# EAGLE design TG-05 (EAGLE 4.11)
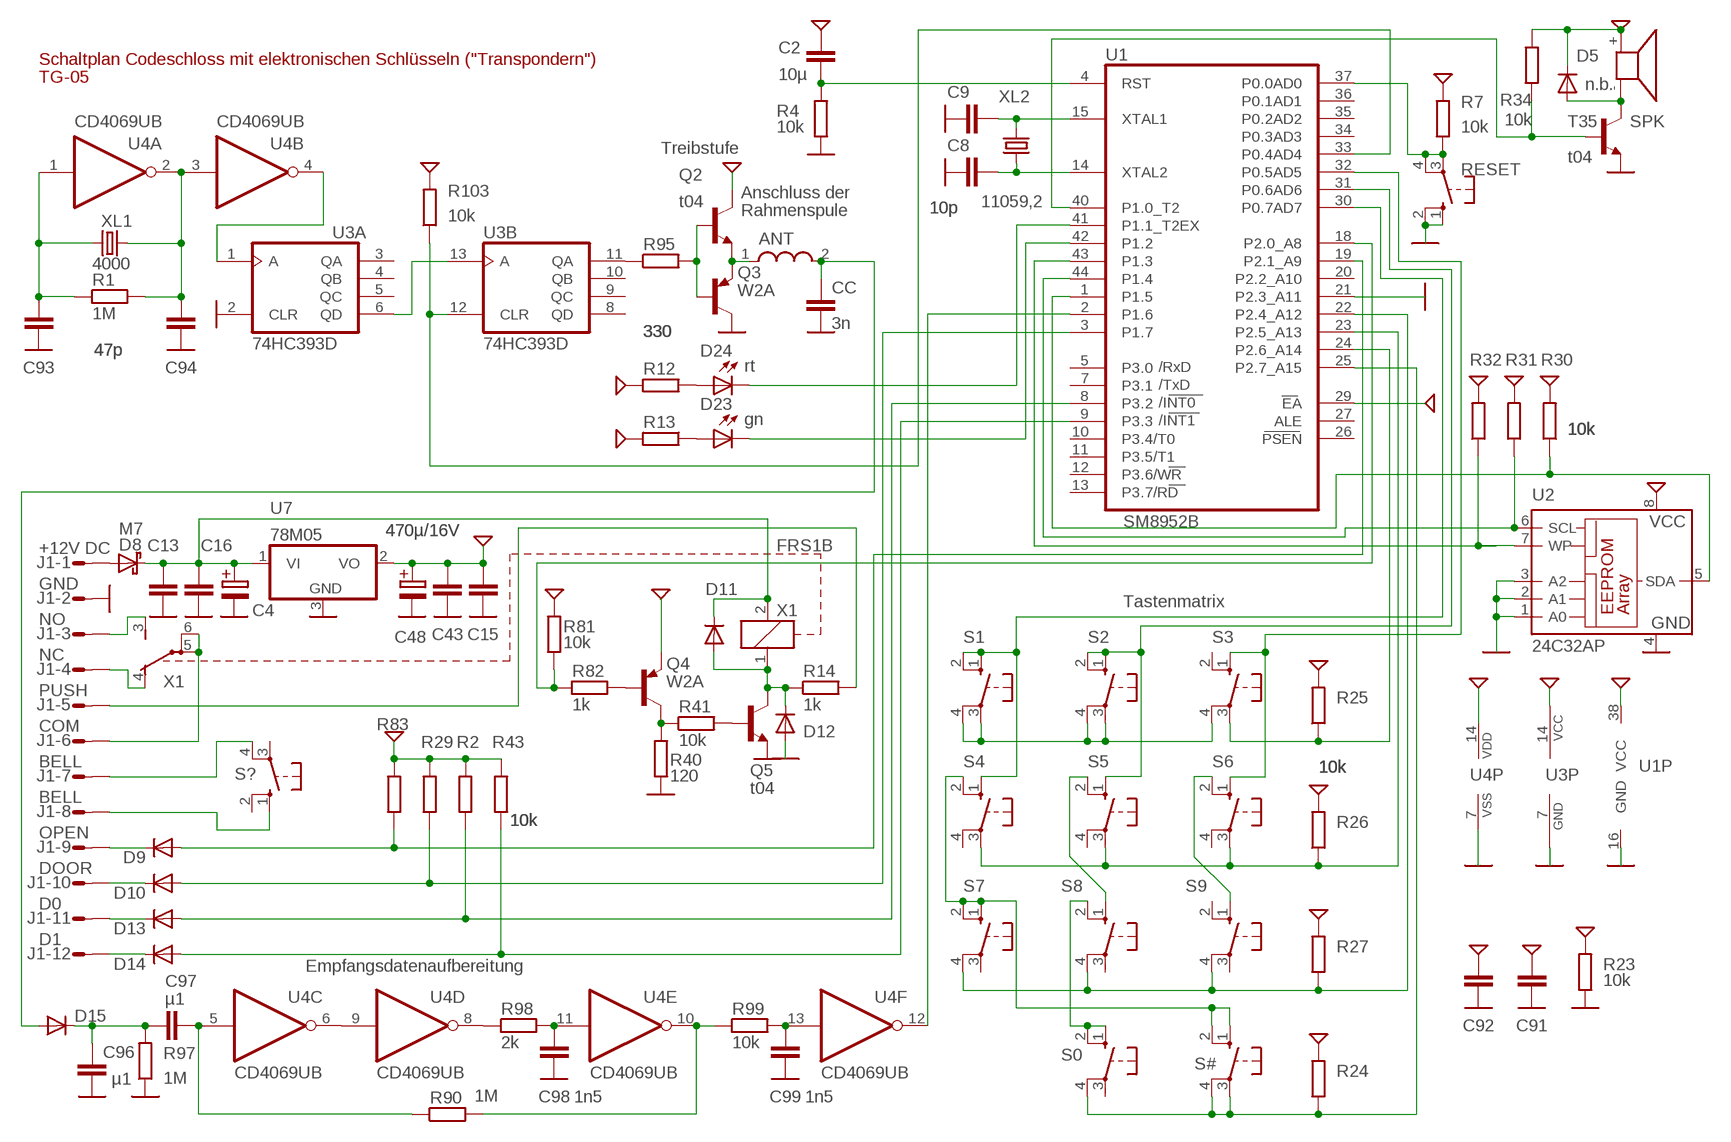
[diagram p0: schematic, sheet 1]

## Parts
ANT  L1206  [1206]
C2  10µ  C0805  [0805]
C4  470µ/16V  E01-5  [E01-5]
C8  10p  C0603  [0603]
C9  10p  C0603  [0603]
C13  C0603  [0603]
C15  C0603  [0603]
C16  C0603  [0603]
C43  C0603  [0603]
C48  470µ/16V  E01-5  [E01-5]
C91  C0603  [0603]
C92  C0603  [0603]
C93  47p  C0603  [0603]
C94  47p  C0603  [0603]
C96  µ1  C0603  [0603]
C97  µ1  C0603  [0603]
C98  1n5  C0603  [0603]
C99  1n5  C0603  [0603]
CC  3n  C1206  [1206]
D5  n.b.  D  [MINIMELF]
D8  M7  DSB  [SMB]
D9  D  [MINIMELF]
D10  D  [MINIMELF]
D11  D  [MINIMELF]
D12  D  [MINIMELF]
D13  D  [MINIMELF]
D14  D  [MINIMELF]
D15  D  [MINIMELF]
D23  gn  LEDCHIP-LED0805  [CHIP-LED0805]
D24  rt  LEDCHIP-LED0805  [CHIP-LED0805]
J1  S12P  [S12P]
Q2  t04  NPN23BEC  [SOT23]
Q3  W2A  PNP23BEC  [SOT23]
Q4  W2A  PNP23BEC  [SOT23]
Q5  t04  NPN23BEC  [SOT23]
R1  1M  R0603  [0603]
R2  10k  R0603  [0603]
R4  10k  R0603  [0603]
R7  10k  R0603  [0603]
R12  330  R0603  [0603]
R13  330  R0603  [0603]
R14  1k  R0603  [0603]
R23  10k  R0603  [0603]
R24  10k  R0603  [0603]
R25  10k  R0603  [0603]
R26  10k  R0603  [0603]
R27  10k  R0603  [0603]
R29  10k  R0603  [0603]
R30  10k  R0603  [0603]
R31  10k  R0603  [0603]
R32  10k  R0603  [0603]
R34  10k  R0603  [0603]
R40  120  R0603  [0603]
R41  10k  R0603  [0603]
R43  10k  R0603  [0603]
R81  10k  R0603  [0603]
R82  1k  R0603  [0603]
R83  10k  R0603  [0603]
R90  1M  R0603  [0603]
R95  330  R0603  [0603]
R97  1M  R0603  [0603]
R98  2k  R0603  [0603]
R99  10k  R0603  [0603]
R103  10k  R0603  [0603]
RESET  10-XX  [B3F-10XX]
S0  10-XXSMD  [B3F-10SMD]
S1  10-XXSMD  [B3F-10SMD]
S2  10-XXSMD  [B3F-10SMD]
S3  10-XXSMD  [B3F-10SMD]
S4  10-XXSMD  [B3F-10SMD]
S5  10-XXSMD  [B3F-10SMD]
S6  10-XXSMD  [B3F-10SMD]
S7  10-XXSMD  [B3F-10SMD]
S8  10-XXSMD  [B3F-10SMD]
S9  10-XXSMD  [B3F-10SMD]
S#  10-XXSMD  [B3F-10SMD]
S?  10-XXSMD  [B3F-10SMD]
SPK  KSS1201  [KSS1201]
T35  t04  NPN23BEC  [SOT23]
U1  SM8952B  AT89C8252Q  [PQFP44]
U2  24C32AP  [DIL8]
U3  74HC393D  74LS393D  [SO14]
U4  CD4069UB  4069D  [SO14]
U7  78M05  7805DT  [TO252]
X1  FRS1B  [FRS1B]
XL1  4000  CRYSTALS  [HC49/S]
XL2  11059,2  CRYSTALS  [HC49/S]

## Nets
5P: C2.1 C15.1 C43.1 C48.+ C91.1 C92.1 D5.K Q2.3(C) Q4.2(E) R2.2 R7.2 R12.2 R13.2 R23.2 R24.2 R25.2 R26.2 R27.2 R29.2 R30.2 R31.2 R32.2 R34.2 R43.2 R81.2 R83.2 R103.2 SPK.+ U1.29(EA) U1.38(VCC) U2.8(VCC) U3.14(P:VCC) U4.14(P:VDD) U7.2(VO)
12P: C4.+ C13.1 C16.1 D8.1(K) D11.K U7.1(VI) X1.2
GND: C4.- C8.2 C9.2 C13.2 C15.2 C16.2 C43.2 C48.- C91.2 C92.2 C93.2 C94.2 C96.2 C98.2 C99.2 CC.2 D12.A J1.2 Q3.3(C) Q5.2(E) R4.1 R23.1 R40.1 R97.1 RESET.1(S) RESET.2(S) T35.2(E) U1.16(GND) U1.21(P2.3_A11) U2.1(A0) U2.2(A1) U2.3(A2) U2.4(GND) U3.2(A:CLR) U3.7(P:GND) U4.7(P:VSS) U7.3(GND)
N$1: ANT.2 CC.1 D15.A
N$2: ANT.1 Q2.2(E) Q3.2(E)
N$3: D8.2(A) J1.1
N$4: D11.A D12.K Q5.3(C) R14.1 X1.1
N$5: C8.1 U1.14(XTAL2) XL2.1
N$6: C9.1 U1.15(XTAL1) XL2.2
N$7: R32.1 U1.43(P1.3) U2.7(WP)
N$8: R34.1 T35.1(B) U1.40(P1.0_T2)
N$9: D24.A R12.1
N$10: D23.A R13.1
N$11: Q5.1(B) R41.2
N$12: Q4.3(C) R40.2 R41.1
N$13: R25.1 S3.3(P) U1.24(P2.6_A14)
N$14: S5.2(S) S8.1(S)
N$15: S1.1(S) S1.2(S) S4.1(S) U1.30(P0.7AD7)
N$16: R30.1 U1.1(P1.5) U2.5(SDA)
N$17: R31.1 U1.44(P1.4) U2.6(SCL)
N$18: R26.1 S4.3(P) S5.3(P) S6.3(P) U1.23(P2.5_A13)
N$19: D24.C U1.41(P1.1_T2EX)
N$20: J1.8 S?.1(S)
N$21: D23.C U1.42(P1.2)
N$22: S3.1(S) S6.1(S) U1.32(P0.5AD5)
N$23: R7.1 RESET.3(P) RESET.4(P) U1.37(P0.0AD0)
N$24: D5.A SPK.- T35.3(C)
N$25: R27.1 S7.4(P) S8.4(P) S9.4(P) U1.22(P2.4_A12)
N$26: R24.1 S0.4(P) S#.3(P) S#.4(P) U1.25(P2.7_A15)
N$27: D9.K J1.9
N$28: J1.7 S?.4(P)
N$29: D10.K J1.10
N$30: D9.A R83.1 U1.19(P2.1_A9)
N$31: R95.1 U3.11(B:QA)
N$32: Q2.1(B) Q3.1(B) R95.2
N$33: D13.K J1.11
N$34: C96.1 C97.1 D15.K R97.2
N$35: C97.2 R90.1 U4.5(C:I)
N$36: R90.2 R99.1 U4.10(E:O)
N$37: C93.1 R1.1 U4.1(A:I) XL1.2
N$38: C98.1 R98.2 U4.11(E:I)
N$39: R98.1 U4.8(D:O)
N$40: U3.6(A:QD) U3.13(B:A)
N$41: U4.6(C:O) U4.9(D:I)
N$42: J1.3 X1.3(2:S)
N$43: J1.4 X1.4(2:O)
N$44: J1.6 X1.5(2:P) X1.6(2:P)
N$45: D14.K J1.12
N$46: J1.5 R14.2
N$47: C94.1 R1.2 U4.2(A:O) U4.3(B:I) XL1.1
N$48: D10.A R29.1 U1.3(P1.7)
N$49: U3.1(A:A) U4.4(B:O)
N$50: C99.1 R99.2 U4.13(F:I)
N$51: U1.2(P1.6) U4.12(F:O)
N$52: R103.1 U1.33(P0.4AD4) U3.12(B:CLR)
N$53: D13.A R2.1 U1.8(P3.2)
N$54: D14.A R43.1 U1.9(P3.3)
N$55: Q4.1(B) R82.2
N$56: R81.1 R82.1 U1.18(P2.0_A8)
N$57: S2.1(S) S2.2(S) S5.1(S) U1.31(P0.6AD6)
N$58: S6.2(S) S9.1(S)
N$59: S4.2(S) S7.1(S) S7.2(S) S#.1(S) S#.2(S)
N$60: S0.1(S) S0.2(S) S8.2(S)
N$61: S1.3(P) S1.4(P) S2.3(P) S2.4(P) S3.4(P)
RESET: C2.2 R4.2 U1.4(RST)
Unconnected: S0.3(P) S3.2(S) S4.4(P) S5.4(P) S6.4(P) S7.3(P) S8.3(P) S9.2(S) S9.3(P) S?.2(S) S?.3(P) U1.5(P3.0) U1.7(P3.1) U1.10(P3.4/T0) U1.11(P3.5/T1) U1.12(P3.6/WR) U1.13(P3.7/RD) U1.20(P2.2_A10) U1.26(PSEN) U1.27(ALE) U1.34(P0.3AD3) U1.35(P0.2AD2) U1.36(P0.1AD1) U3.3(A:QA) U3.4(A:QB) U3.5(A:QC) U3.8(B:QD) U3.9(B:QC) U3.10(B:QB)

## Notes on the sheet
- Schaltplan Codeschloss mit elektronischen Schlüsseln ("Transpondern")
- TG-05
- Treibstufe
- Anschluss der
- Rahmenspule
- +12V DC
- GND
- Tastenmatrix
- NO
- NC
- PUSH
- COM
- BELL
- BELL
- OPEN
- DOOR
- D0
- D1
- Empfangsdatenaufbereitung

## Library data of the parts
ANT = Ofen:L: Drossel
C2 C8 C9 C13 C15 C16 C43 C91-C94 C96-C99 CC = Ofen:C: Kondensator
C4 C48 = Ofen:E: Elektrolytkondensator
D5 D9-D15 = Ofen:D: Diode
D8 = Ofen:DS: Schottky-Diode
D23 D24 = led:LED: LED
J1 = con-amp-mt:S12P: AMP MT CONNECTOR
Q2 Q5 T35 = Ofen:NPN: NPN-Transistor Verschiedene Bauformen und Leistungen
Q3 Q4 = Ofen:PNP: PNP-Transistor Verschiedene Bauformen und Leistungen
R1 R2 R4 R7 R12-R14 R23-R27 R29-R32 R34 R40 R41 R43 R81-R83 R90 R95 R97-R99 R103 = Ofen:R: Widerstand
RESET S0 S1-S9 S# S? = Ofen:10-XX: Drucktaster
SPK = buzzer:KSS1201: SPEAKER
U1 = atmel:AT89C*52: MICROCONTROLLER 8 Kbytes FLASH; 2K Bytes EEPROM Compatible with MCS-51 Products at89s8252.pdf
U2 = microchip:24*: Serial EEPROM I2C
U3 = 74xx-us:74*393: Dual 4-bit decade and binary COUNTER
U4 = 40xx:4069: Hex INVERTER
U7 = linear:78*: Positive VOLTAGE REGULATOR
X1 = Ofen:FRS1B: Relais, 1 Umschaltkontakt
XL1 XL2 = Ofen:CRYSTAL: Quarz

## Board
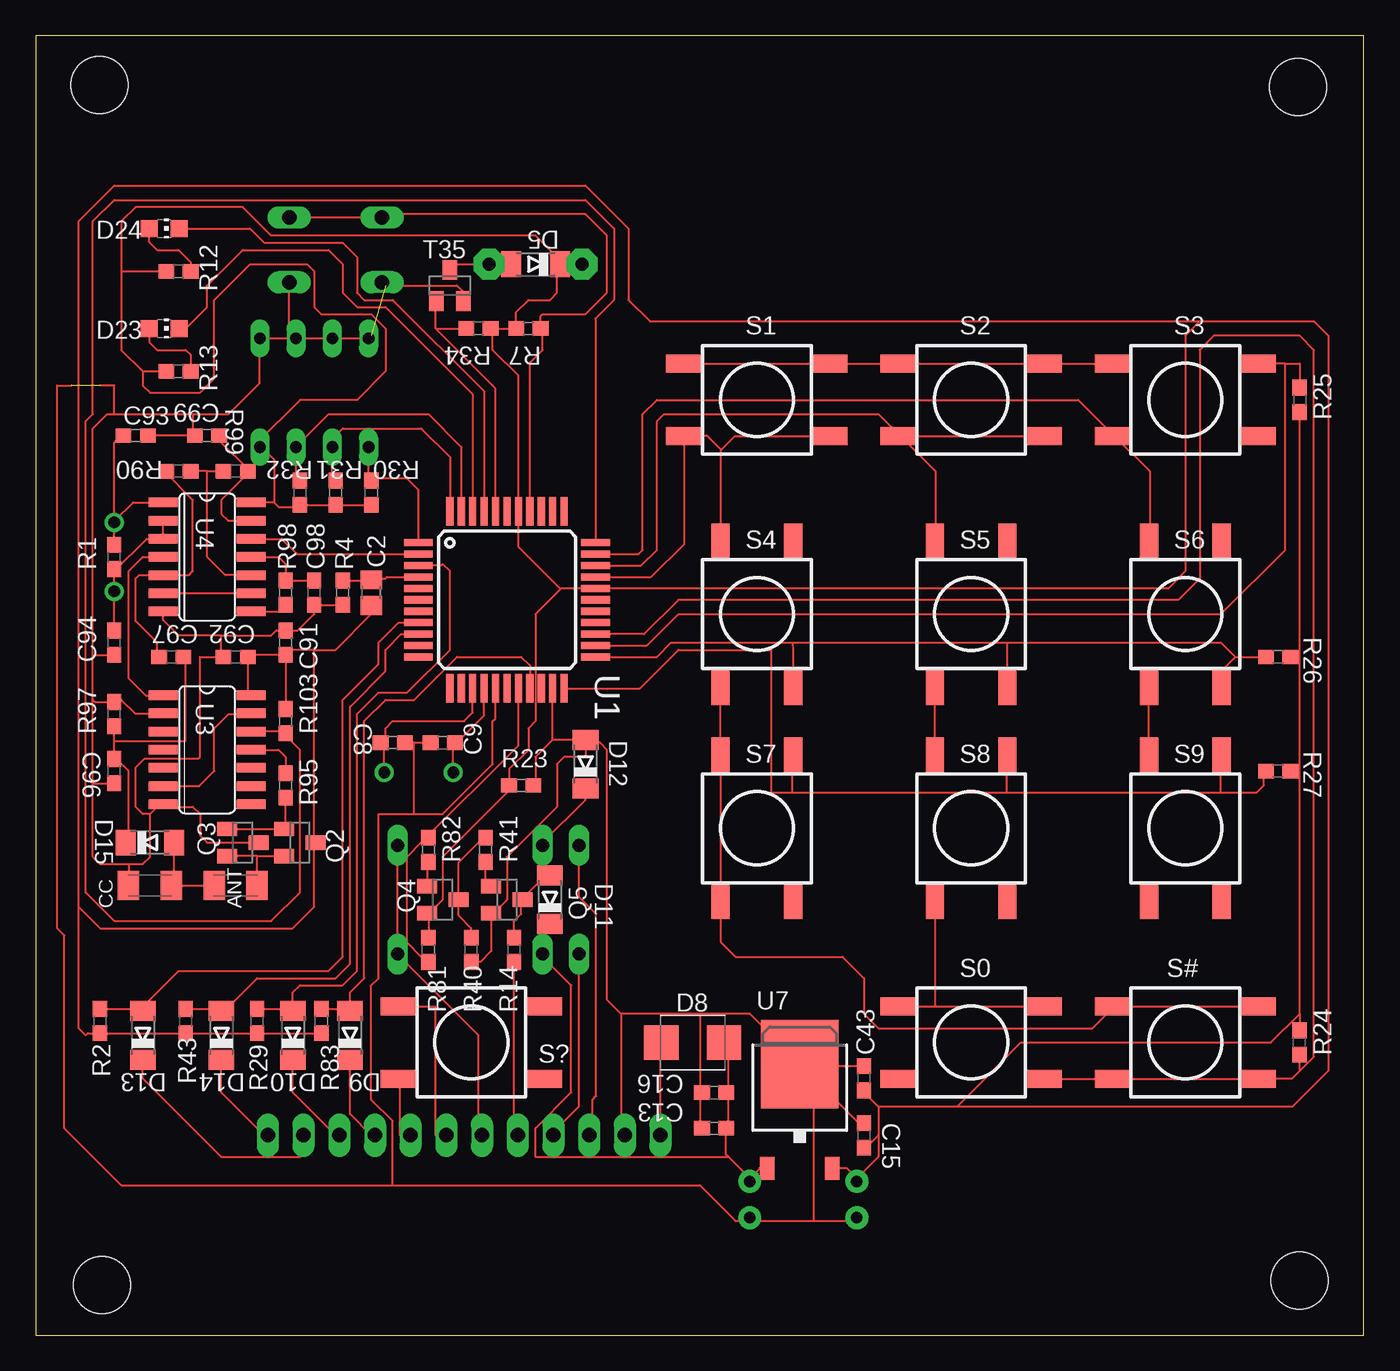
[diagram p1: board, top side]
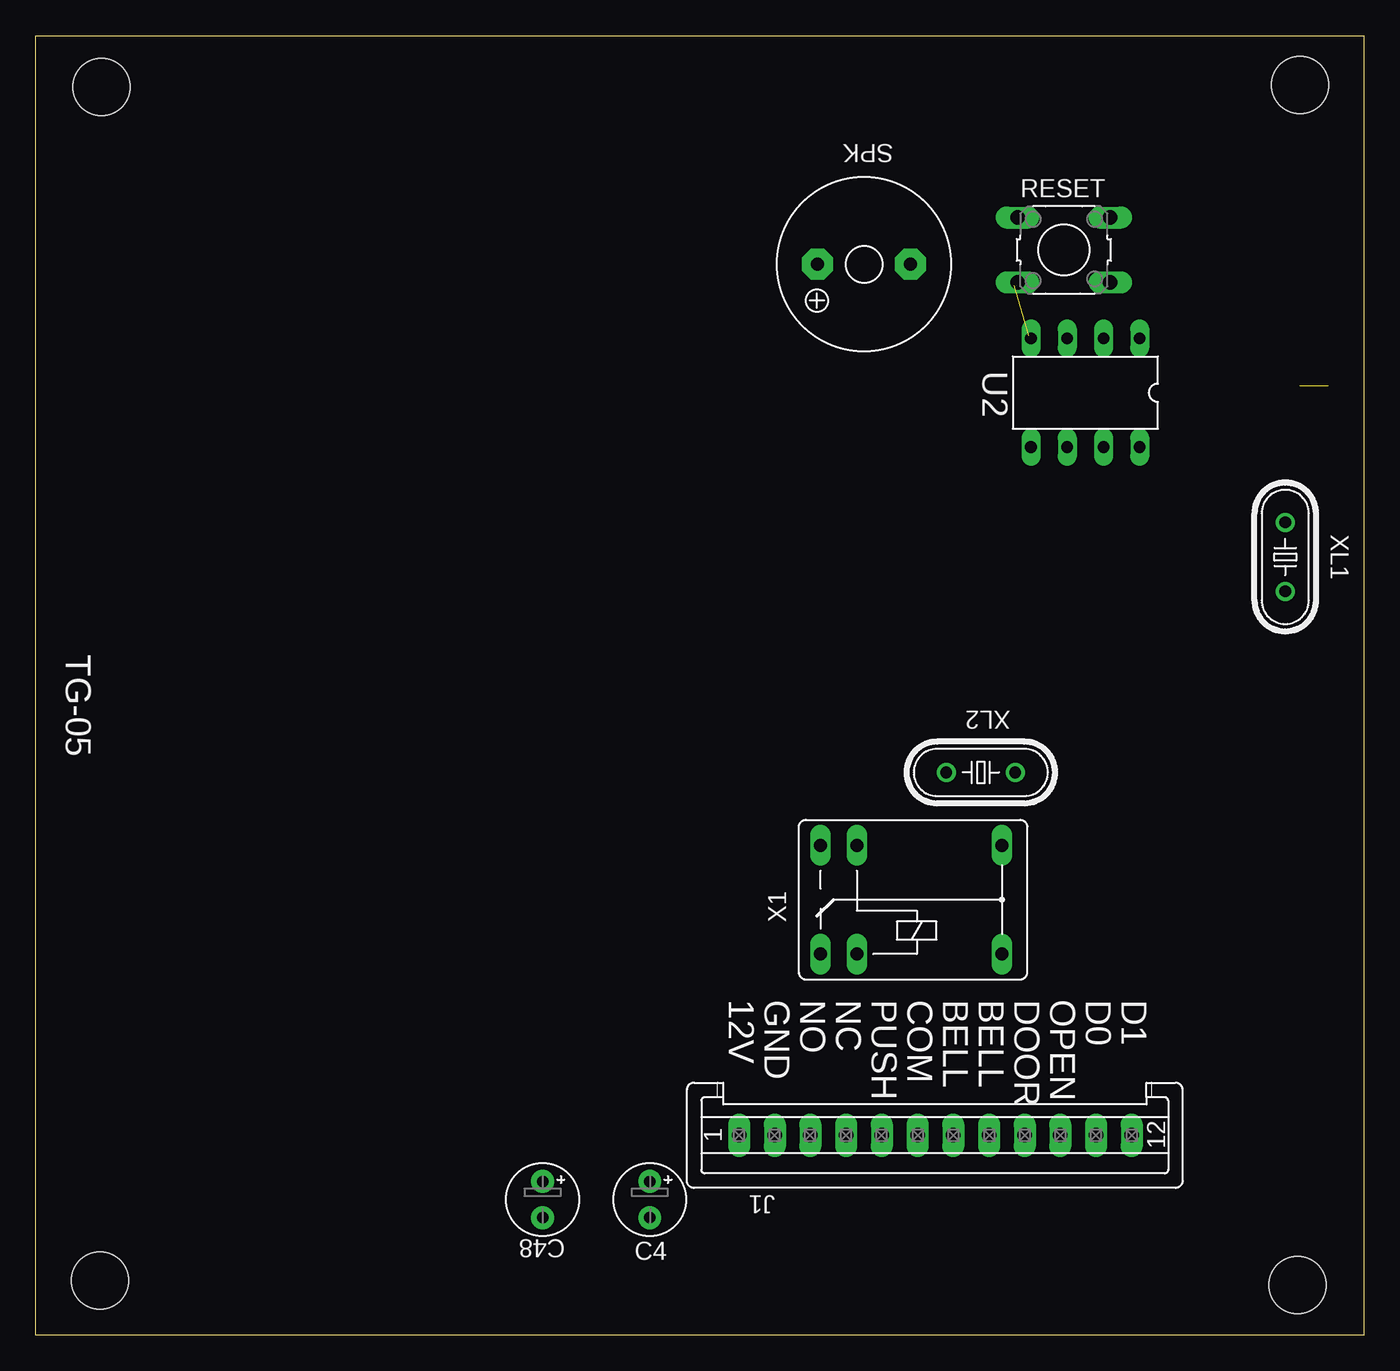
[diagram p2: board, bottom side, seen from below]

Size 93 x 91 mm. Coordinates in mm from the lower left corner, seen from the top.
Outline: 0,0 93,0 93,91 0,91 0,0
Copper layers (1+16): Top 0.035mm / dielectric 1mm / Bottom 0.035mm
Design rules "default": minimum track width 0.15mm, minimum drill 0.6mm, track to track 8mil, track to pad 8mil, pad to pad 8mil, via to via 8mil, smd to smd 0mil, copper to edge 0mil, drill to drill 8mil, minimum pad ring 10mil, minimum via ring 8mil, stop-mask expansion 4mil, vias tented up to drill 0mil, thermal gap 10mil
Holes 4 mm at 4.63,3.53 88.49,3.84 88.4,87.4 4.46,87.54

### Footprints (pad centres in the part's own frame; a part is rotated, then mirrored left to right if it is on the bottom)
1206 = smd 1.5 x 2: 1 -1.5,0; 2 1.5,0
0805 = smd 1.3 x 1.5: 1 -0.9,0; 2 0.9,0
E01-5 = drill 0.813 pad 1.6 round: + -1.27,0; - 1.27,0
0603 = smd 1.1 x 1: 1 -0.85,0; 2 0.85,0
MINIMELF = smd 1.4 x 1.8: A 1.7,0; K -1.7,0
SMB = smd 2.4 x 2.4: 1 -2.2,0; 2 2.2,0
CHIP-LED0805 = smd 1.2 x 1.2: A 0,-1.05; C 0,1.05
S12P = drill 1.016 long: 1 13.75,0; 2 11.25,0; 3 8.75,0; 4 6.25,0; 5 3.75,0; 6 1.25,0; 7 -1.25,0; 8 -3.75,0; 9 -6.25,0; 10 -8.75,0; 11 -11.25,0; 12 -13.75,0
SOT23 = smd 1 x 1.4: 1 -0.95,-1.1; 2 0.95,-1.1; 3 0,1.1
B3F-10XX = drill 1.016 long: 1 -3.251,-2.261; 2 3.251,-2.261; 3 3.251,2.261; 4 -3.251,2.261
B3F-10SMD = smd 2.54 x 1.27: 1 -5.08,-2.54; 2 5.08,-2.54; 3 5.08,2.54; 4 -5.08,2.54
KSS1201 = drill 0.914 pad 2.159 octagon: + 3.251,0; - -3.251,0
PQFP44 = smd 2 x 0.5: 1 -6.2,4; 2 -6.2,3.2; 3 -6.2,2.4; 4 -6.2,1.6; 5 -6.2,0.8; 6 -6.2,0; 7 -6.2,-0.8; 8 -6.2,-1.6; 9 -6.2,-2.4; 10 -6.2,-3.2; 11 -6.2,-4; 23 6.2,-4; 24 6.2,-3.2; 25 6.2,-2.4; 26 6.2,-1.6; 27 6.2,-0.8; 28 6.2,0; 29 6.2,0.8; 30 6.2,1.6; 31 6.2,2.4; 32 6.2,3.2; 33 6.2,4 | smd 0.5 x 2: 12 -4,-6.2; 13 -3.2,-6.2; 14 -2.4,-6.2; 15 -1.6,-6.2; 16 -0.8,-6.2; 17 0,-6.2; 18 0.8,-6.2; 19 1.6,-6.2; 20 2.4,-6.2; 21 3.2,-6.2; 22 4,-6.2; 34 4,6.2; 35 3.2,6.2; 36 2.4,6.2; 37 1.6,6.2; 38 0.8,6.2; 39 0,6.2; 40 -0.8,6.2; 41 -1.6,6.2; 42 -2.4,6.2; 43 -3.2,6.2; 44 -4,6.2
DIL8 = drill 0.813 long: 1 -3.81,-3.81; 2 -1.27,-3.81; 3 1.27,-3.81; 4 3.81,-3.81; 5 3.81,3.81; 6 1.27,3.81; 7 -1.27,3.81; 8 -3.81,3.81
SO14 = smd 0.66 x 2.032: 1 -3.81,-3.073; 2 -2.54,-3.073; 3 -1.27,-3.073; 4 0,-3.073; 5 1.27,-3.073; 6 2.54,-3.073; 7 3.81,-3.073; 8 3.81,3.073; 9 2.54,3.073; 10 1.27,3.073; 11 0,3.073; 12 -1.27,3.073; 13 -2.54,3.073; 14 -3.81,3.073
TO252 = smd 1 x 1.6: 1 -2.28,-4.8; 2 2.28,-4.8 | smd 5.4 x 6.2: 3 0,2.5
FRS1B = drill 0.914 long: 1 0,3.81; 2 0,-3.81; 3 -2.54,3.81; 4 -2.54,-3.81; 5 10.16,3.81; 6 10.16,-3.81
HC49/S = drill 0.813 round: 1 -2.413,0; 2 2.413,0

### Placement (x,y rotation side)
ANT  14,31.5 180 top
C2  23.5,52 90 top
C4  50,9.5 270 bottom
C8  25,41.5 0 top
C9  28.5,41.5 180 top
C13  47.5,14.5 180 top
C15  58,14 90 top
C16  47.5,17 180 top
C43  58,18 90 top
C48  57.5,9.5 270 bottom
C91  17.5,48.5 90 top
C92  14,47.5 180 top
C93  7,63 0 top
C94  5.5,48.5 270 top
C96  5.5,39.5 270 top
C97  9.5,47.5 180 top
C98  19.5,52 270 top
C99  12,63 180 top
CC  8,31.5 180 top
D5  35,75 180 top
D8  46,20.5 180 top
D9  22,21 90 top
D10  18,21 90 top
D11  36,30.5 90 top
D12  38.5,40 90 top
D13  7.5,21 90 top
D14  13,21 90 top
D15  8,34.5 0 top
D23  9,70.5 270 top
D24  9,77.5 270 top
J1  30,14 180 bottom
Q2  18.5,34.5 270 top
Q3  14.5,34.5 270 top
Q4  28.5,30.5 270 top
Q5  33,30.5 270 top
R1  5.5,54.5 270 top
R2  4.5,22 270 top
R4  21.5,52 90 top
R7  34.5,70.5 180 top
R12  10,74.5 180 top
R13  10,67.5 180 top
R14  33.5,27 270 top
R23  34,38.5 180 top
R24  88.5,20.5 90 top
R25  88.5,65.5 270 top
R26  87,47.5 0 top
R27  87,39.5 0 top
R29  15.5,22 270 top
R30  23.5,59 270 top
R31  21,59 270 top
R32  18.5,59 270 top
R34  31,70.5 0 top
R40  30.5,27 90 top
R41  31.5,34 270 top
R43  10.5,22 270 top
R81  27.5,27 90 top
R82  27.5,34 270 top
R83  20,22 270 top
R90  10,60.5 0 top
R95  17.5,38.5 270 top
R97  5.5,43.5 270 top
R98  17.5,52 90 top
R99  14,60.5 0 top
R103  17.5,43 90 top
RESET  21,76 0 bottom
S0  65.5,20.5 180 top
S1  50.5,65.5 0 top
S2  65.5,65.5 0 top
S3  80.5,65.5 0 top
S4  50.5,50.5 270 top
S5  65.5,50.5 270 top
S6  80.5,50.5 270 top
S7  50.5,35.5 270 top
S8  65.5,35.5 270 top
S9  80.5,35.5 270 top
S#  80.5,20.5 180 top
S?  30.5,20.5 0 top
SPK  35,75 180 bottom
T35  29,73.5 0 top
U1  33,51.5 0 top
U2  19.5,66 180 bottom
U3  12,41 270 top
U4  12,54.5 270 top
U7  53.5,16.5 0 top
X1  35.5,30.5 0 bottom
XL1  5.5,54.5 90 bottom
XL2  26.82,39.41 180 bottom

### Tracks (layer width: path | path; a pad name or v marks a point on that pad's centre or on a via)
5P
  Top 0.15: 88.5,47.5 R25.2 | 88.5,47.5 R26.2 | 88.5,39.5 R27.2 | 88.5,39.5 88.5,47.5 | 88.5,22.5 R24.2 | 88.5,22.5 88.5,39.5 | 81.5,71 80.5,70 80.5,53.5 79.3,52.3 U1.29 36.8,52.3 36.75,52.25 | 81.5,71 89.5,71 90.5,70 90.5,18.5 88,16 64.5,16 | 64.5,16 69,20.5 86.5,20.5 88.5,22.5 | C43.1 58,17 59,16 | 64.5,16 59,16 | C15.1 58,13 59,14 | 59,16 59,14 | 59,14 59,12.5 57.5,11 56.8,11.7 U7.2 | 37,75 D5.K | 37,75 SPK.+ | 32,70.5 R34.2 | 32,70.5 32,69 33.8,67.2 U1.38 33.8,55.2 36.75,52.25 | 32,70.5 R7.2 33.65,71.65 34.5,72.5 36,72.5 36.5,73 36.5,74.5 37,75 | 16.69,58.31 U4.14 | 16.69,58.31 17,58 18.5,58 R32.2 20.85,58.15 21,58 R31.2 23.35,58.15 23.5,58 R30.2 | 15.69,62.31 15.5,62.5 18.5,65.5 22.5,65.5 24.5,67.5 24.5,70.5 23.5,71.5 20,71.5 19.5,72 19.5,74.5 19,75 15,75 12.5,72.5 12.5,67 11.5,66 8,66 7.5,66.5 7.5,67.5 | 15.69,62.31 U2.8 | 16.69,58.31 16.69,61.31 15.69,62.31 | 6,74.5 R12.2 | 6,74.5 6,69 7.5,67.5 | 7.5,67.5 R13.2 | 6,74.5 6,78 7,79 14.5,79 16.5,77 35,77 37,75 | U3.14 15.07,44.93 14.85,45.15 C92.1 15,47.5 15.15,47.65 C91.1 | C91.1 R103.2 | C2.1 23.5,50.5 21,48 19.5,48 | C91.1 17.5,48 19.5,48 | 27.5,29.55 Q4.2 | 27.5,29.55 27.55,29.55 28.5,30.5 28.5,33.5 33,38 33,38.5 R23.2 33.15,39.65 34.5,41 34.5,42.5 35,43 35,50.5 36.75,52.25 | 81.5,71 43,71 41.5,72.5 41.5,77.5 38.5,80.5 5.5,80.5 3,78 3,30 | 3,30 3,21.5 3.5,21 3.65,21.15 R2.2 10.35,21.15 10.5,21 | 10.5,21 R43.2 | 10.5,21 10.65,21.15 R29.2 20.35,21.15 20.5,21 R83.2 | 3,30 4.5,28.5 18,28.5 19.5,30 19.5,34.5 | 19.5,34.5 Q2.3 | 19.5,34.5 19.5,48 | 27.5,29.55 R81.2
  Bottom 0.15: 57.5,11 C48.+
12P
  Top 0.15: 48.5,17 C16.1 | D8.1 48.5,20.5 48.5,17 | 48.5,17 48.5,14.5 C13.1 48.35,12.65 48.5,12.5 | 48.5,12.5 50,11 50.7,11.7 U7.1 | D11.K 36,28.5 35.5,28 X1.2 35.5,26.5 37.5,24.5 37.5,17 35,14.5 35,12.5 48.5,12.5
  Bottom 0.15: 50,11 C4.+
GND  (2 unrouted)
  Top 0.15: C43.2 53.65,18.85 U7.3 | C15.2 57.65,14.85 54.5,18 | 54.5,18 U7.3 | C13.2 46.5,14.5 46.5,17 | 46.5,17 C16.2 | 46.5,22.5 46.5,17 | 46.5,22.5 50,22.5 U7.3 | 46.5,22.5 41,22.5 | J1.2 41.5,14 41,14.5 41,22.5 | 11,63 C93.2 | 11,63 C99.2 | 18,69.5 18.23,69.73 U2.2 | 17.75,69.75 17.69,69.81 U2.1 15.69,66.69 13.5,64.5 11,64.5 | 17.75,69.75 18,69.5 | 17.75,69.75 18,70 18.19,69.81 U2.3 U2.4 23.5,70 | RESET.2 17.75,69.75 18,69.5 | T35.2 29.95,73.05 29.5,73.5 24.5,73.5 RESET.1 | 11,64.5 11,63 | 5.5,64.5 11,64.5 | 5.5,64.5 5.5,66.5 4.5,66.5 | 54.5,8 57.5,8 | 54.5,8 54.5,18 | 54.5,8 49,8 46.5,10.5 25,10.5 | 25,10.5 6,10.5 2,14.5 2,28 1.5,28.5 1.5,66.5 2.5,66.5 | U3.2 6.96,43.54 6,44.5 5.5,44.5 R97.1 4.15,44.35 4,44.5 | 4,44.5 4,47.5 | C94.2 4.15,47.65 4,47.5 | 5.5,64.5 5,64.5 4,63.5 4,47.5 | 4,38.65 C96.2 | 4,38.65 4,44.5 | 6.5,33 CC.2 | 6.5,33 4.5,33 4,33.5 4,38.65 | 6.5,33 7.5,33 8,33.5 8,36.5 | 8,36.5 8.69,37.19 U3.7 8.93,37.07 9,37 11,37 11.5,36.5 11.5,35 12,34.5 Q3.3 | 8,36.5 7.5,36.5 7,37 7,39.75 7.62,40.38 11.38,40.38 11.5,40.5 11.5,47.5 13,47.5 | U4.7 8.93,50.07 10,49 13,49 | 13,47.5 C92.2 | 13,49 16.5,49 16.85,49.35 C91.2 18.35,49.35 19.5,50.5 19.5,51 | 13,47.5 13,49 | 19.5,51 C98.2 | R4.1 19.65,51.15 19.5,51 | 36.2,41.7 U1.21 | R23.1 35,38.5 35,40.5 36.2,41.7 | 36.2,41.7 D12.A 38.5,41.5 | 38.5,41.5 38.5,40.5 37,40.5 36.5,40 36.5,37 33,33.5 33,30.5 32.05,29.55 Q5.2 31.9,26.9 31.15,26.15 R40.1 | 38.5,41.5 39.5,41.5 40,41 40,23.5 41,22.5 | 25,10.5 25,15 23.5,16.5 23.5,24.5 24,25 24,36.5 26.5,36.5 | 26.5,36.5 28.5,36.5 32,40 32,43 32.2,43.2 U1.16 | 26.5,41.5 C8.2 | 26.5,41.5 C9.2 | 26.5,36.5 26.5,41.5
  Bottom 0.15: 50,8 C4.- | 57.5,8 C48.-
N$1
  Top 0.15: ANT.2 CC.1 9.7,31.7 D15.A
N$2
  Top 0.15: 17.45,33.55 Q2.2 | 15.5,33.55 Q3.2 | 15.5,33.55 17.45,33.55 | 17.45,33.55 17.5,33.5 | ANT.1 15.5,33.55
N$3
  Top 0.15: D8.2 44,20.5 43.75,20.25 J1.1
N$4
  Top 0.15: D12.K 38.5,37.5 35.5,34.5 X1.1 35.5,32.5 36,32.5 D11.A 35.7,32.2 34,30.5 | 34,30.5 Q5.3 | R14.1 33.5,29 34,29.5 34,30.5
N$5
  Top 0.15: C8.1 24,41.5 24.25,41.25 | XL2.1 24.41,41.09 24.25,41.25 | U1.14 30.6,43.6 30,43 25,43 24.5,42.5 24.5,41.5 24.25,41.25
N$6
  Top 0.15: 29.5,41.5 C9.1 | XL2.2 29.23,41.23 29.5,41.5 | U1.15 31.4,43.4 29.5,41.5
N$7
  Top 0.15: R32.1 18.5,60 18.23,60.27 U2.7 18.23,62.23 20.5,64.5 27.5,64.5 29.8,62.2 U1.43
N$8
  Top 0.15: 28,70.5 R34.1 | T35.1 28.05,72.05 28,72 28,70.5 | 28,70.5 32,66.5 32.2,66.3 U1.40
N$9
  Top 0.15: D24.A 7.95,76.55 8.5,76 10,76 10.85,75.15 R12.1
N$10
  Top 0.15: D23.A 7.95,69.55 8.5,69 10.5,69 10.85,68.65 R13.1
N$11
  Top 0.15: Q5.1 31.55,31.45 31.5,31.5 R41.2
N$12
  Top 0.15: R41.1 31.5,35 29.6,33.1 Q4.3 29.6,29.4 30.5,28.5 R40.2
N$13
  Top 0.15: 87.49,68.04 S3.3 | 87.49,68.04 88.5,68.04 R25.1 | 87.49,68.04 87.49,54.99 83,50.5 45,50.5 42.8,48.3 U1.24
N$14
  Top 0.15: S8.1 62.96,40.54 | 62.96,40.54 S5.2 | 62.96,40.54 63,40.5
N$15
  Top 0.15: U1.30 43.1,53.1 45.42,55.42 S1.1 45.46,62.96 45.5,63 47,63 47.96,62.04 47.96,62 | 47.96,62 S4.1 | 47.96,62 48,62 48.96,62.96 S1.2
N$16
  Top 0.15: 23.5,60 R30.1 | U2.5 23.31,60.19 23.5,60 | U1.1 26.8,59.2 26,60 23.5,60
N$17
  Top 0.15: R31.1 21,60 20.77,60.23 U2.6 20.77,62.23 20.5,62.5 21.5,63.5 27,63.5 29,61.5 U1.44
N$18
  Top 0.15: 84,47.5 R26.1 | S6.3 83.04,46.54 84,47.5 | U1.23 43.5,47.5 44.5,48.5 53,48.5 | S4.3 53.04,47.96 53,48.5 | 84,47.5 83,48.5 68,48.5 | S5.3 68.04,45.46 68,45.5 68,48.5 | 53,48.5 68,48.5
N$19
  Top 0.15: D24.C 15,77.5 16,76.5 21.5,76.5 22.5,75.5 22.5,73 23,72.5 25,72.5 31.4,66.1 U1.41
N$20
  Top 0.15: 25.5,17.96 25.5,18 | 25.5,17.96 S?.1 | J1.8 25.5,14 25.5,17.96
N$21
  Top 0.15: U1.42 30.6,65.9 24.5,72 22.5,72 21.5,73 21.5,75 20.5,76 14.5,76 12,73.5 12,72 10.5,70.5 D23.C
N$22
  Top 0.15: U1.32 42.2,54.7 42.5,55 42.5,64.5 43.5,65.5 73,65.5 75.5,63 75.46,62.96 S3.1 75.54,62.96 78,60.5 78,55.5 77.96,55.54 S6.1
N$23
  Top 0.15: RESET.4 23.94,78.56 24,78.5 24.5,78.5 | 24.5,78.5 38.5,78.5 40,77 40,73 38.5,71.5 35.5,71.5 35.35,71.35 R7.1 35,70.5 35.5,70 35.5,69 34.6,68.1 U1.37 | RESET.3 RESET.4 24.5,78.5
N$24
  Top 0.15: D5.A SPK.- 29,75 T35.3
N$25
  Top 0.15: U1.22 42.3,45.3 45,48 51.5,48 51.5,38 53,38 | S7.4 53.04,40.54 53,40.5 53,38 | 53,38 68,38 | S8.4 68.04,40.54 68,40.5 68,38 | 68,38 83,38 | S9.4 83.04,40.54 83,40.5 83,38 | 83,38 85.5,38 86,38.5 86,39.5 R27.1
N$26
  Top 0.15: S0.4 70.54,17.96 | 70.46,17.96 70.5,18 70.54,17.96 | 70.54,17.96 S#.3 85.46,17.96 85.5,18 | 85.5,18 85.54,17.96 S#.4 | 88.5,18.5 R24.1 | 88.5,18.5 88,18 85.5,18 | 88.5,18.5 89.5,19.5 89.5,69 88.5,70 82.5,70 81.5,69 81.5,53 80,51.5 45,51.5 42.6,49.1 U1.25
N$27
  Top 0.15: J1.9 23.5,14 22,15.5 D9.K
N$28
  Top 0.15: J1.7 28,14 28,23 25.5,23 25.5,23.04 S?.4
N$29
  Top 0.15: J1.10 21,14 18,17 D10.K
N$30
  Top 0.15: 22,23 D9.A | R83.1 21.85,22.85 22,23 | U1.19 34.6,46.9 34,47.5 29.5,47.5 26.5,44.5 24.5,44.5 23,43 23,25 22,24 22,23
N$31
  Top 0.15: U3.11 17,41 17.5,40.5 R95.1
N$32
  Top 0.15: 17.45,35.45 Q2.1 | Q3.1 17.45,35.45 | 17.45,35.45 17.5,35.5 R95.2
N$33
  Top 0.15: J1.11 18.75,12.75 18.5,12.5 13,12.5 7.5,18 D13.K
N$34
  Top 0.15: 5.5,41.62 C96.1 5.65,40.35 6.5,39.5 6.5,34.5 D15.K | 5.5,41.62 R97.2 | 5.5,41.62 10.5,41.62 10.5,47.5 C97.1
N$35
  Top 0.15: C97.2 8.5,47.5 8.5,48.5 7,50 7,53 7.23,53.23 U4.5 10.73,53.23 11,53.5 11,58.5 9,60.5 R90.1
N$36
  Top 0.15: 12,60.5 R99.1 | 12,60.5 R90.2 | U4.10 13.27,53.23 12,54.5 12,60.5
N$37
  Top 0.15: U4.1 6.81,58.31 5.5,57 | C93.1 6,63 5.5,62.5 5.5,57 | 5.5,57 XL1.2 | R1.1 5.5,57
N$38
  Top 0.15: U4.11 17,54.5 17.5,54 17.5,53 | 17.5,53 R98.2 | C98.1 17.65,52.85 17.5,53
N$39
  Top 0.15: R98.1 17.5,51 17.19,50.69 U4.8
N$40
  Top 0.15: U3.6 11.46,38.46 12.5,39.5 12.5,42.5 13.5,43.5 15,43.5 15.04,43.54 U3.13
N$41
  Top 0.15: U4.9 15.04,51.96 15,52 14.96,51.96 U4.6
N$42
  Top 0.15: X1.3 38.04,30.71 39.25,29.5 39.25,16.75 39,16.5 39,14 J1.3
N$43
  Top 0.15: X1.4 38.04,16.04 36,14 J1.4
N$44
  Top 0.15: X1.5 X1.6 25.34,26.66 | 25.34,26.66 25.5,26.5 | 25.34,26.66 31,21 31,14 J1.6
N$45
  Top 0.15: J1.12 16,14 13,17 D14.K
N$46
  Top 0.15: J1.5 33.5,14 R14.2
N$47
  Top 0.15: 5.5,53.5 XL1.1 C94.1 | 5.5,53.5 R1.2 | 5.5,53.5 7.77,55.77 U4.3 8.93,55.93 9,56 8.93,56.07 U4.2
N$48
  Top 0.15: R29.1 17.85,22.85 18,23 D10.A 18,24 18.5,24.5 21.5,24.5 22.5,25.5 22.5,43.5 24,45 26,45 29,48 29,53.5 28.5,54 28.4,53.9 U1.3
N$49
  Top 0.15: U4.4 7.5,54.5 6.5,53.5 6.5,46 7.69,44.81 U3.1
N$50
  Top 0.15: 15,60.5 R99.2 | C99.1 12.85,62.65 15,60.5 | U4.13 13.46,57.04 13,57.5 13,58.5 15,60.5
N$51
  Top 0.15: U4.12 17.23,55.77 18.3,54.7 U1.2
N$52
  Top 0.15: 17.5,42 R103.1 | U3.12 17.23,42.27 17.5,42 | U1.33 39.2,71.2 40.5,72.5 40.5,77.5 38.5,79.5 5.5,79.5 4,78 4,64.5 3.5,64 3.5,31 5.5,29 16.5,29 18.5,31 18.5,41 17.5,42
N$53
  Top 0.15: 7.5,23 D13.A | R2.1 7.35,22.85 7.5,23 | U1.8 25.4,49.9 24,48.5 24,47 21.5,44.5 21.5,26.5 20.5,25.5 10,25.5 7.5,23
N$54
  Top 0.15: 13,23 D14.A | R43.1 12.85,22.85 13,23 | U1.9 25.6,49.1 24.5,48 24.5,46.5 22,44 22,26 21,25 15.5,25 13.5,23 13,23
N$55
  Top 0.15: R82.2 27.5,33 27.4,32.6 Q4.1
N$56
  Top 0.15: 27,34.5 26,33.5 26,27.5 27,26.5 R81.1 | U1.18 33.8,41.3 27,34.5 | 27,34.5 R82.1
N$57
  Top 0.15: 60.5,63 60.46,62.96 S2.1 | 60.54,62.96 S2.2 | 60.5,63 60.54,62.96 | 60.54,62.96 63,60.5 63,55.5 62.96,55.54 S5.1 | U1.31 42.4,53.9 43.5,55 43.5,64 44,64.5 59,64.5 60.5,63
N$58
  Top 0.15: 77.96,45.46 S6.2 | S9.1 77.96,45.46 | 77.96,45.46 78,45.5
N$59
  Top 0.15: 47.96,40.54 S7.1 | 47.96,40.54 S4.2 | 47.96,40.54 48,40.5 48,30.5 | S#.2 75.04,23.04 75,23 | S#.2 S#.1 | S#.2 75.42,22.92 74,21.5 59,21.5 58,22.5 58,25 56.5,26.5 49,26.5 48,27.5 48,30.5 | S7.2 47.96,30.46 48,30.5
N$60
  Top 0.15: S0.2 62.96,23.04 63,23 | S8.2 62.96,30.46 63,30.5 63,23 | S0.1 63.04,23.04 63,23
N$61
  Top 0.15: S1.4 S1.3 S2.4 S2.3 S3.4
RESET
  Top 0.15: 23.5,53 C2.2 | R4.2 23.35,52.85 23.5,53 | U1.4 24.6,53.1 24.5,53 23.5,53

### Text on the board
bPlace: TG-05 | D1 | D0 | OPEN | DOOR | BELL | BELL | COM | PUSH | NC | NO | GND | 12V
